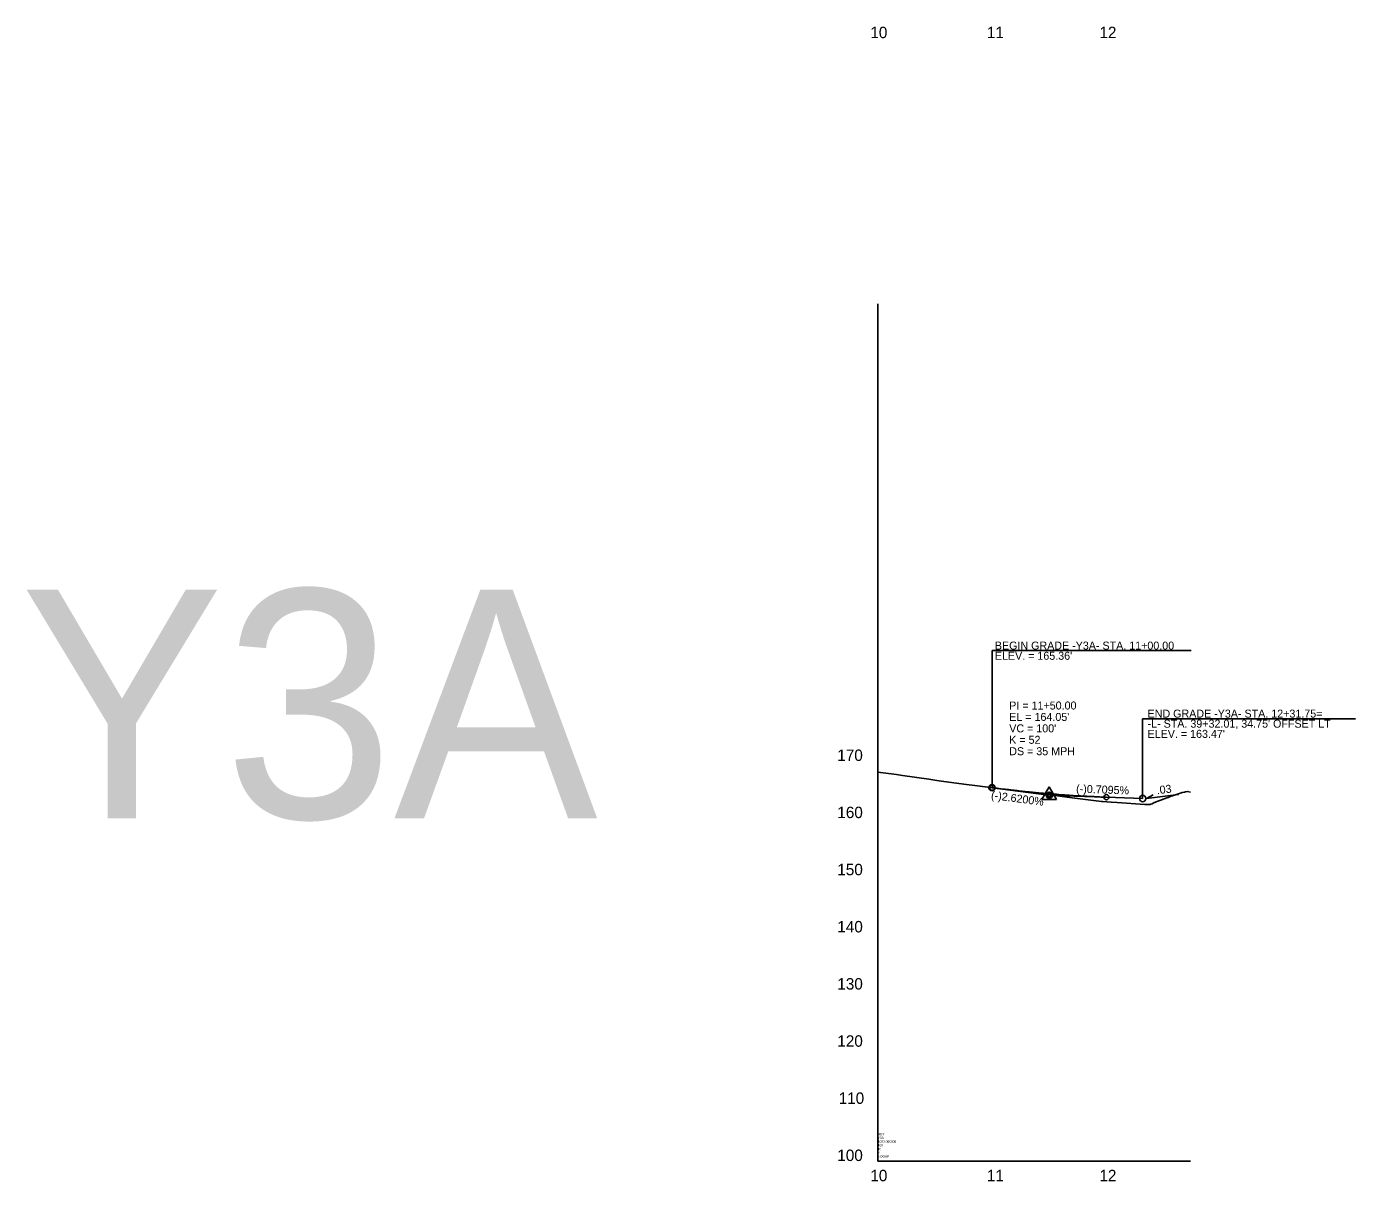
# Model space of a CAD drawing. Extents: x 1778432 to 1784301, y 601022 to 621789.
# Drawn here: x 1779398 to 1780561, y 614022 to 615032 of the extents above; entities that cross this region are included whole.
import ezdxf

# ---------------------------------------------------------------- set-up
doc = ezdxf.new("R2010")
doc.units = 0
for name, color, linetype in [('Exist Profile Cell', 7, 'Continuous'), ('Exist Vertical Profile Ground Line', 7, 'Continuous'), ('Exist Vertical Profile Horizontal Axis Label Major', 7, 'Continuous'), ('Exist Vertical Profile Vertical Axis Label', 7, 'Continuous'), ('Prop PFL Text', 7, 'Continuous'), ('Prop PFL VPI Symbol CELL', 7, 'Continuous'), ('Prop Vertical Profile Curve Label', 7, 'Continuous'), ('Prop Vertical Profile Grade', 7, 'Continuous'), ('Prop Vertical Profile Grade Label', 7, 'Continuous'), ('Prop VPI Label', 7, 'Continuous')]:
    doc.layers.add(name, color=color, linetype=linetype)

msp = doc.modelspace()

# ---------------------------------------------------------------- linework, layer by layer
at = {"layer": 'Exist Profile Cell'}
for q in [(1780143, 614789.2), (1780416.4, 614039.2), (1780143, 614039.2)]:
    msp.add_line((1780143, 614039.2), q, dxfattribs=at)
at = {"layer": 'Exist Vertical Profile Ground Line'}
msp.add_lwpolyline([(1780143, 614379.7), (1780159.4, 614377.4), (1780164.7, 614376.6), (1780187.6, 614373.4), (1780194.7, 614372.3), (1780200.7, 614371.5), (1780220.7, 614368.9), (1780228, 614368), (1780250.7, 614365), (1780254.4, 614364.6), (1780275.4, 614361.9), (1780278.8, 614361.7), (1780304.2, 614358.4), (1780308.6, 614357.7), (1780308.9, 614357.6), (1780312.9, 614357.1), (1780338.7, 614353.9), (1780339.5, 614353.9), (1780347.1, 614353.3), (1780352.3, 614352.9), (1780376.7, 614351.2), (1780379, 614351.2), (1780381.3, 614351.2), (1780381.8, 614351.6), (1780382.9, 614352), (1780384.8, 614352.9), (1780385.4, 614353.1), (1780386.4, 614353.5), (1780388, 614354.1), (1780388.9, 614354.5), (1780390.6, 614355.2), (1780392.5, 614355.9), (1780393.4, 614356.3), (1780395.7, 614357.1), (1780396.9, 614357.5), (1780398.3, 614358.1), (1780400.4, 614358.8), (1780400.9, 614359), (1780402.5, 614359.5), (1780403.5, 614359.8), (1780403.8, 614359.9), (1780406.1, 614360.7), (1780407.4, 614361.1), (1780408.6, 614361.5), (1780409.4, 614361.7), (1780411.2, 614362.2), (1780412.1, 614362.5), (1780413.8, 614362.8), (1780416.4, 614362)], dxfattribs=at)
at = {"layer": 'Prop PFL VPI Symbol CELL'}
for p, q in [((1780292.9, 614366.8), (1780286.5, 614355.6)), ((1780286.5, 614355.6), (1780299.4, 614355.6)), ((1780292.9, 614366.8), (1780299.4, 614355.6))]:
    msp.add_line(p, q, dxfattribs=at)
for radius in [1.75, 1.2]:
    msp.add_circle((1780292.9, 614359.3), radius, dxfattribs=at)
at = {"layer": 'Prop Vertical Profile Curve Label'}
for centre in [(1780243, 614366), (1780343, 614357.7)]:
    msp.add_circle(centre, 2.25, dxfattribs=at)
at = {"layer": 'Prop Vertical Profile Grade'}
msp.add_line((1780343, 614357.7), (1780374.7, 614356.5), dxfattribs=at)
msp.add_spline([(1780243, 614366), (1780245, 614365.8), (1780247, 614365.5), (1780249, 614365.2), (1780251, 614365), (1780253, 614364.7), (1780255, 614364.5), (1780257, 614364.3), (1780259, 614364), (1780261, 614363.8), (1780263, 614363.6), (1780265, 614363.4), (1780267, 614363.1), (1780269, 614362.9), (1780271, 614362.7), (1780273, 614362.5), (1780275, 614362.3), (1780277, 614362.1), (1780279, 614361.9), (1780281, 614361.7), (1780283, 614361.5), (1780285, 614361.3), (1780287, 614361.2), (1780289, 614361), (1780291, 614360.8), (1780293, 614360.6), (1780295, 614360.5), (1780297, 614360.3), (1780299, 614360.2), (1780301, 614360), (1780303, 614359.8), (1780305, 614359.7), (1780307, 614359.6), (1780309, 614359.4), (1780311, 614359.3), (1780313, 614359.2), (1780315, 614359), (1780317, 614358.9), (1780319, 614358.8), (1780321, 614358.7), (1780323, 614358.6), (1780325, 614358.5), (1780327, 614358.4), (1780329, 614358.3), (1780331, 614358.2), (1780333, 614358.1), (1780335, 614358), (1780337, 614357.9), (1780339, 614357.8), (1780341, 614357.7), (1780343, 614357.7)], degree=3, dxfattribs=at)
at = {"layer": 'Prop VPI Label'}
for p, q in [((1780243, 614366), (1780243, 614486)), ((1780243, 614486), (1780417.2, 614486)), ((1780374.7, 614356.5), (1780374.7, 614426.2)), ((1780374.7, 614426.2), (1780560.8, 614426.2)), ((1780243, 614366), (1780290.2, 614359.8)), ((1780343, 614357.7), (1780295.7, 614359.3)), ((1780378.1, 614356.6), (1780406.1, 614360.1)), ((1780378.1, 614356.6), (1780383.9, 614359.8))]:
    msp.add_line(p, q, dxfattribs=at)
for centre in [(1780243, 614366), (1780293, 614359.4), (1780374.7, 614356.5)]:
    msp.add_circle(centre, 2.75, dxfattribs=at)

# ---------------------------------------------------------------- texts
at = {"layer": 'Exist Profile Cell'}
for s, p in [('Y3A', (1780143, 614058.7)), ('RDY', (1780143, 614061.9)), ('1000.000000', (1780143, 614055.4)), ('100', (1780143, 614052.2)), ('2', (1780143, 614045.7)), ('10', (1780143, 614048.9)), ('NOGAP', (1780143, 614042.4))]:
    msp.add_text(s, height=2, dxfattribs=at).set_placement(p)
at = {"layer": 'Exist Vertical Profile Horizontal Axis Label Major'}
for s, p in [('10', (1780136.5, 615021.7)), ('11', (1780238.4, 615021.7)), ('12', (1780336.9, 615021.7)), ('10', (1780136.5, 614021.7)), ('11', (1780238.4, 614021.7)), ('12', (1780336.9, 614021.7))]:
    msp.add_text(s, height=10, dxfattribs=at).set_placement(p)
at = {"layer": 'Exist Vertical Profile Vertical Axis Label'}
for s, p in [('170', (1780107.6, 614389.4)), ('160', (1780107.6, 614339.4)), ('150', (1780107.6, 614289.4)), ('140', (1780107.6, 614239.4)), ('130', (1780107.6, 614189.4)), ('120', (1780107.6, 614139.4)), ('110', (1780108.8, 614089.4)), ('100', (1780107.6, 614039.4))]:
    msp.add_text(s, height=10, dxfattribs=at).set_placement(p)
at = {"layer": 'Prop PFL Text'}
msp.add_text('Y3A', height=200, dxfattribs=at).set_placement((1779392.6, 614339.2))
at = {"layer": 'Prop Vertical Profile Curve Label'}
for s, p in [("VC = 100'", (1780258, 614414.4)), ('K = 52', (1780258, 614404.4)), ('DS = 35 MPH', (1780258, 614394.4))]:
    msp.add_text(s, height=7, dxfattribs=at).set_placement(p)
at = {"layer": 'Prop Vertical Profile Grade Label'}
for s, rotation, p in [('(-)0.7095%', 357.9774, (1780316.4, 614361.7)), ('.03', 7.125, (1780387.4, 614360.2)), ('(-)2.6200%', 352.4951, (1780241.8, 614356.2))]:
    msp.add_text(s, height=7, rotation=rotation, dxfattribs=at).set_placement(p)
at = {"layer": 'Prop VPI Label'}
for s, p in [('BEGIN GRADE -Y3A- STA. 11+00.00', (1780245.4, 614486.8)), ("ELEV. = 165.36'", (1780245.4, 614477.9)), ('PI = 11+50.00', (1780258, 614434.4)), ("EL = 164.05'", (1780258, 614424.4)), ("-L- STA. 39+32.01, 34.75' OFFSET LT", (1780379, 614418.5)), ('END GRADE -Y3A- STA. 12+31.75=', (1780379, 614427.3)), ("ELEV. = 163.47'", (1780379, 614409.6))]:
    msp.add_text(s, height=7, dxfattribs=at).set_placement(p)

doc.saveas('drawing.dxf')
